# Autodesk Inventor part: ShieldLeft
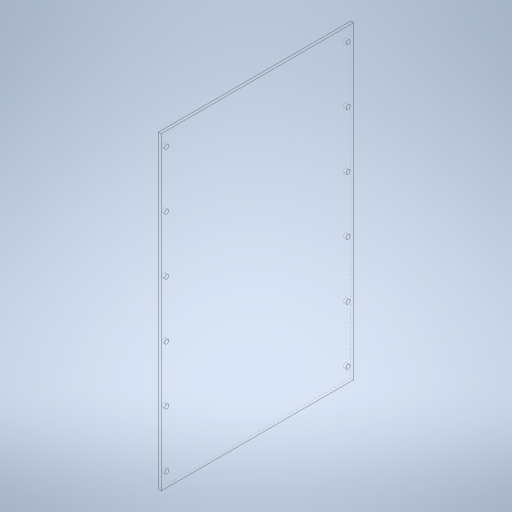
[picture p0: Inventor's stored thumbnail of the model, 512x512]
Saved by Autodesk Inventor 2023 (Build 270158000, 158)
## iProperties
Created: 2023-10
Part Number: ShieldLeft
Material: Aluminum 7075
Document SubType Name: Modeling
Designer: tornqvih
Density: 2.81 g/cm^3
Appearance: Satin - Brushed Heavy
Author: tornqvih
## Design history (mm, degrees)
sketch "Sketch1"
  geometry: L1 (110, 68.5)-(-110, 68.5); L2 (-110, 68.5)-(-110, -68.5); L3 (-110, -68.5)-(110, -68.5); L4 (110, -68.5)-(110, 68.5); L5 (110, 68.5)-(-110, -68.5); L6 (-110, 68.5)-(110, -68.5); 1 further point
  constraints: 12 end point, 2 midpoint, 2 parallel, 1 horizontal, 1 perpendicular
  dimensions: "d0" = 137 distance of L3.end L1.start; "d1" = 220 distance of L1.start L1.end
extrude "Extrusion1" new body sketch "Sketch1" distance "d2" = 2; taper "d3" = 0 deg
sketch "Sketch2"
  geometry: L1 (68.5, 110)-(-68.5, 110) reference; L2 (-68.5, 110)-(-68.5, -110) reference; L3 (0, -154)-(0, 154) reference; 15 further points; 1 other entity
  constraints: 6 vertical alignment, 5 symmetric about line, 1 other
  dimensions: "d5" = 4 distance from line of L2 point (-64.5, 100); "d13" = 20 dimension on point (-64.5, 20); "d14" = 60 dimension on point (-64.5, 60); "d15" = 100 dimension on point (-64.5, 100)
hole "Hole1" sketch "Sketch2" at (-64.5, 100), (-64.5, 20), (-64.5, -100), (64.5, 100), (64.5, 20), (64.5, -100), (-64.5, -20), (64.5, -20), (-64.5, 60), (64.5, 60), (64.5, -60), (-64.5, -60) diameter "d6" = 3; stored, may be unused: countersink angle "d10" = 90 deg, drill point angle "d12" = 118 deg; dims "d7" = 6, "d8" = 4, "d9" = 2, "d11" = 8
body "Solid1"
